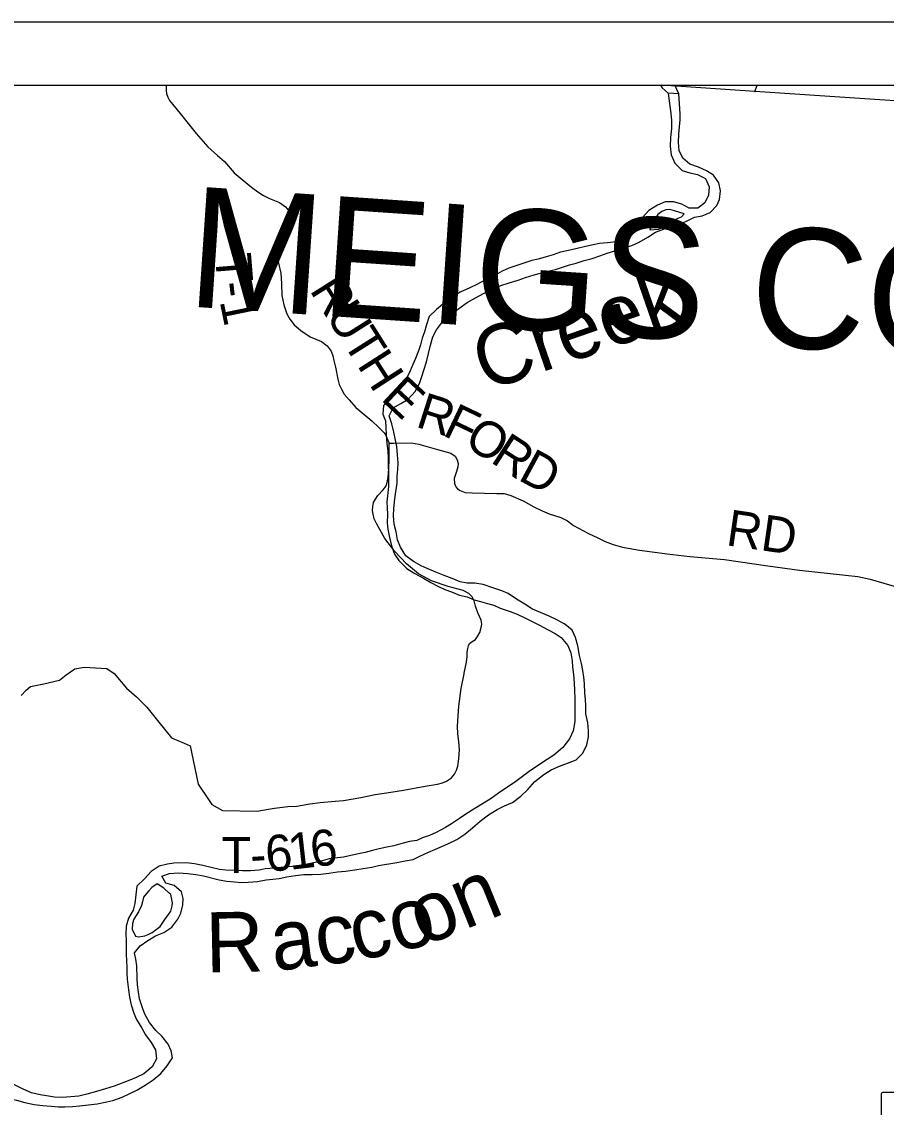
# Model space of a CAD drawing. Extents: x -15 to 405, y -40 to 87.
# Drawn here: x -11.81 to -10.448, y 27.988 to 29.698 of the extents above; entities that cross this region are included whole.
import ezdxf

# ---------------------------------------------------------------- set-up
doc = ezdxf.new("R2010")
doc.units = 0
for name, color, linetype in [('GM_P_State_Location', 7, 'Continuous'), ('GM_P_US_Location', 7, 'Continuous'), ('GM_X_County_Road_Text', 7, 'Continuous'), ('GM_X_Minor_River', 7, 'Continuous'), ('GM_X_Township', 7, 'Continuous'), ('GM_X_Township_Road', 7, 'Continuous'), ('GM_X_Township_Road_Text', 7, 'Continuous'), ('GM_X_Township_Subdivision', 7, 'Continuous')]:
    doc.layers.add(name, color=color, linetype=linetype)

msp = doc.modelspace()

# ---------------------------------------------------------------- linework, layer by layer
at = {"layer": 'GM_P_State_Location'}
msp.add_line((-10.6552, 29.5879), (-10.6519, 29.5981), dxfattribs=at)
for points in [[(-11.5825, 29.5981), (-11.5827, 29.5959), (-11.5829, 29.5898), (-11.5822, 29.585), (-11.5804, 29.5795), (-11.5773, 29.5742), (-11.5608, 29.5537), (-11.5354, 29.522), (-11.5169, 29.5009), (-11.5018, 29.4872), (-11.4911, 29.4778), (-11.4755, 29.4603), (-11.4632, 29.4494), (-11.4485, 29.4374), (-11.4383, 29.4301), (-11.4296, 29.4245), (-11.4199, 29.4195), (-11.404, 29.4132), (-11.3947, 29.4065), (-11.3897, 29.4003), (-11.3867, 29.3929), (-11.3872, 29.3858), (-11.3887, 29.3786), (-11.3902, 29.3734), (-11.3936, 29.3662), (-11.3978, 29.3581), (-11.4042, 29.3457), (-11.4063, 29.339), (-11.4075, 29.3323), (-11.4074, 29.3244), (-11.4056, 29.3176), (-11.4022, 29.3021), (-11.4012, 29.2857), (-11.4007, 29.2671), (-11.3973, 29.2521), (-11.3925, 29.2382), (-11.3879, 29.2297), (-11.3811, 29.2209), (-11.3708, 29.2117), (-11.356, 29.202), (-11.3383, 29.1942), (-11.3291, 29.1875), (-11.323, 29.179), (-11.3201, 29.1718), (-11.3184, 29.1645), (-11.3161, 29.1539), (-11.3122, 29.135), (-11.3101, 29.1269), (-11.3064, 29.1192), (-11.3021, 29.1117), (-11.2947, 29.1024), (-11.2838, 29.0905), (-11.2589, 29.0692), (-11.2477, 29.0588), (-11.2396, 29.0505), (-11.2368, 29.0469), (-11.2354, 29.0429), (-11.2317, 29.0344), (-11.2244, 29.0342), (-11.1962, 29.0347), (-11.1847, 29.0329), (-11.1551, 29.0245), (-11.1343, 29.0186), (-11.1275, 29.0138), (-11.1241, 29.0081), (-11.1228, 29.0021), (-11.1231, 28.997), (-11.1255, 28.9894), (-11.1289, 28.9784), (-11.1283, 28.9706), (-11.1266, 28.9657), (-11.1238, 28.9623), (-11.1198, 28.9595), (-11.1119, 28.9568), (-11.1006, 28.9558), (-11.0618, 28.9551), (-11.0502, 28.9548), (-11.0397, 28.9517), (-11.0203, 28.9432), (-11.0033, 28.9342), (-10.9902, 28.9275), (-10.9793, 28.9228), (-10.9608, 28.917), (-10.9506, 28.9121), (-10.9413, 28.9047), (-10.9176, 28.892), (-10.9026, 28.8849), (-10.8911, 28.8793), (-10.8785, 28.8744), (-10.8639, 28.8704), (-10.8373, 28.8658), (-10.7934, 28.86), (-10.758, 28.856), (-10.7029, 28.8512), (-10.6349, 28.8408), (-10.5852, 28.8343), (-10.5127, 28.8264), (-10.4933, 28.824), (-10.4737, 28.8203), (-10.4521, 28.8139), (-10.4196, 28.8042)], [(-11.5153, 28.4715), (-11.5111, 28.4652), (-11.4938, 28.4557), (-11.4397, 28.4547), (-11.4123, 28.4592), (-11.3913, 28.4619), (-11.3768, 28.4626), (-11.3562, 28.4661), (-11.3401, 28.4684), (-11.3166, 28.4702), (-11.3034, 28.4714), (-11.276, 28.476), (-11.2536, 28.481), (-11.2287, 28.4845), (-11.2087, 28.4877), (-11.1748, 28.494), (-11.1554, 28.4969), (-11.1473, 28.499), (-11.1409, 28.502), (-11.1331, 28.5069), (-11.1284, 28.5127), (-11.1252, 28.5193), (-11.1232, 28.5253), (-11.1216, 28.5373), (-11.1209, 28.5514), (-11.1216, 28.5645), (-11.1232, 28.5763), (-11.1239, 28.5885), (-11.1229, 28.6046), (-11.1215, 28.6199), (-11.1181, 28.6478), (-11.1135, 28.6711), (-11.1134, 28.6719), (-11.1098, 28.6895), (-11.1088, 28.6983), (-11.1084, 28.7049), (-11.1075, 28.7109), (-11.1066, 28.7151), (-11.1047, 28.7185), (-11.1006, 28.7217), (-11.0957, 28.725), (-11.0923, 28.7296), (-11.0886, 28.7361), (-11.0863, 28.7437), (-11.0856, 28.749), (-11.0867, 28.7556), (-11.0918, 28.767), (-11.0955, 28.7776), (-11.0973, 28.7858), (-11.1006, 28.7921), (-11.1061, 28.7976), (-11.1151, 28.8024), (-11.1384, 28.8085), (-11.1649, 28.8174), (-11.185, 28.8285), (-11.2043, 28.8444), (-11.2227, 28.8635), (-11.2384, 28.8843), (-11.2514, 28.9076), (-11.2552, 28.9152), (-11.2567, 28.9223), (-11.2578, 28.9283), (-11.2573, 28.9339), (-11.2562, 28.9406), (-11.2532, 28.9459), (-11.2493, 28.9517), (-11.2407, 28.9608), (-11.2363, 28.9669), (-11.2347, 28.9721), (-11.2333, 28.9802), (-11.2322, 28.9939), (-11.2315, 29.0086), (-11.2317, 29.022), (-11.2317, 29.0344)], [(-11.8113, 28.6369), (-11.8035, 28.645), (-11.7967, 28.6508), (-11.7755, 28.655), (-11.7508, 28.6611), (-11.7401, 28.6693), (-11.7267, 28.6788), (-11.7116, 28.6813), (-11.694, 28.6805), (-11.6761, 28.6793), (-11.6649, 28.6712), (-11.6454, 28.6486), (-11.6295, 28.6347), (-11.613, 28.6182), (-11.5943, 28.595), (-11.5745, 28.5702), (-11.5546, 28.5618), (-11.5452, 28.5576), (-11.5323, 28.497), (-11.5153, 28.4715)]]:
    msp.add_lwpolyline(points, dxfattribs=at)
at = {"layer": 'GM_X_County_Road_Text'}
msp.add_lwpolyline([(-7.293, 29.3749), (-7.5587, 29.3922), (-8.2163, 29.4345), (-8.9822, 29.4843), (-9.3083, 29.5055), (-9.3253, 29.5066), (-9.7655, 29.5289), (-10.6554, 29.5884), (-10.8023, 29.5981)], dxfattribs=at)
at = {"layer": 'GM_X_Township'}
for p, q in [((-14.193, 29.6981), (-7.193, 29.6981)), ((-14.093, 29.5981), (-7.293, 29.5981))]:
    msp.add_line(p, q, dxfattribs=at)
at = {"layer": 'GM_X_Township_Road'}
for q in [(-10.7921, 29.5855), (-10.7813, 29.5981)]:
    msp.add_line((-10.7753, 29.5844), q, dxfattribs=at)
for points in [[(-10.7921, 29.5855), (-10.7876, 29.5535), (-10.7864, 29.5425), (-10.7864, 29.53), (-10.7883, 29.5159), (-10.7886, 29.5019), (-10.7874, 29.4883), (-10.7813, 29.4754), (-10.7696, 29.4637), (-10.7575, 29.4599), (-10.7457, 29.4577), (-10.7332, 29.4509), (-10.7271, 29.438), (-10.7282, 29.4247), (-10.7339, 29.4129), (-10.7452, 29.4042), (-10.7589, 29.4045), (-10.7702, 29.4106), (-10.7835, 29.4143), (-10.7967, 29.4143), (-10.8085, 29.4093), (-10.8221, 29.4006), (-10.833, 29.3892), (-10.8417, 29.3774), (-10.8492, 29.3645), (-10.8613, 29.3542), (-10.8738, 29.3515), (-10.8874, 29.3496), (-10.9003, 29.3488), (-10.9102, 29.3469), (-10.9219, 29.3438), (-10.9351, 29.3407), (-10.9491, 29.3377), (-10.9616, 29.335), (-10.9733, 29.3308), (-10.9839, 29.3277), (-10.9968, 29.3239), (-11.0066, 29.3219), (-11.0429, 29.3097), (-11.0535, 29.3051), (-11.0645, 29.2987), (-11.0785, 29.2922), (-11.0932, 29.2842), (-11.1042, 29.2788), (-11.1197, 29.272), (-11.1329, 29.2643), (-11.1439, 29.256), (-11.1567, 29.2449), (-11.1684, 29.2339), (-11.1733, 29.2191), (-11.176, 29.2096), (-11.1794, 29.1998), (-11.182, 29.1891), (-11.1854, 29.1796), (-11.1899, 29.1675), (-11.194, 29.158), (-11.1997, 29.1443), (-11.2065, 29.1326), (-11.2163, 29.1189), (-11.2291, 29.1067), (-11.2404, 29.0934), (-11.2416, 29.0798), (-11.2374, 29.0695), (-11.2366, 29.0597), (-11.2362, 29.0468), (-11.235, 29.0339), (-11.2335, 29.0214), (-11.2331, 29.0115), (-11.233, 28.999), (-11.2326, 28.9865), (-11.2326, 28.9661), (-11.2341, 28.9513), (-11.2352, 28.9418), (-11.2348, 28.9323), (-11.234, 28.9225), (-11.2344, 28.9084), (-11.2336, 28.8989), (-11.2309, 28.8857), (-11.2278, 28.8724), (-11.2233, 28.8596), (-11.2161, 28.8497), (-11.2035, 28.8369), (-11.191, 28.8289), (-11.1774, 28.8214), (-11.1656, 28.8146), (-11.155, 28.8089), (-11.144, 28.804), (-11.1334, 28.7999), (-11.1205, 28.795), (-11.1088, 28.792), (-11.0974, 28.7875), (-11.0876, 28.7849), (-11.0766, 28.7819), (-11.0664, 28.7789), (-11.0565, 28.7743), (-11.0406, 28.7691), (-11.0296, 28.7649), (-11.0175, 28.7593), (-11.0073, 28.754), (-10.9948, 28.7476)], [(-10.8039, 29.5981), (-10.8013, 29.594), (-10.7921, 29.5855)], [(-10.7728, 29.5529), (-10.7753, 29.5844)], [(-10.9429, 28.7398), (-10.9546, 28.7492), (-10.9672, 28.756), (-10.9793, 28.7617), (-11.0058, 28.773), (-11.0179, 28.7809), (-11.0308, 28.7884), (-11.0441, 28.7975), (-11.0539, 28.8016), (-11.068, 28.8065), (-11.0835, 28.8114), (-11.0967, 28.8137), (-11.1085, 28.814), (-11.1198, 28.8159), (-11.132, 28.8211), (-11.1448, 28.8256), (-11.1577, 28.8309), (-11.1714, 28.8369), (-11.1808, 28.8411), (-11.1933, 28.8479), (-11.2051, 28.8569), (-11.2138, 28.8702), (-11.2184, 28.8819), (-11.2203, 28.8948), (-11.2234, 28.9069), (-11.2245, 28.9198), (-11.2242, 28.9316), (-11.2223, 28.9467), (-11.2208, 28.9577), (-11.219, 28.971), (-11.2186, 28.9824), (-11.2179, 28.993), (-11.2175, 29.0033), (-11.2183, 29.0161), (-11.2195, 29.029), (-11.2241, 29.0518), (-11.2275, 29.0646), (-11.2313, 29.0771), (-11.2253, 29.0897), (-11.2132, 29.0965), (-11.2015, 29.1034), (-11.1905, 29.1156), (-11.1837, 29.1285), (-11.1804, 29.1379), (-11.1762, 29.1509), (-11.1725, 29.1626), (-11.1661, 29.1884), (-11.1627, 29.2017), (-11.157, 29.2127), (-11.1476, 29.2252), (-11.1355, 29.2363), (-11.1219, 29.2462), (-11.1087, 29.2557), (-11.0955, 29.2633), (-11.0818, 29.2705), (-11.0679, 29.277), (-11.0554, 29.2828), (-11.0425, 29.2866), (-11.0281, 29.2908), (-11.0168, 29.295), (-11.0032, 29.2992), (-10.993, 29.3019), (-10.9816, 29.3053), (-10.9695, 29.308), (-10.9597, 29.3107), (-10.9476, 29.3153), (-10.9366, 29.318), (-10.9241, 29.3218), (-10.9116, 29.3252), (-10.8995, 29.3294), (-10.8882, 29.3337), (-10.8761, 29.3371), (-10.8636, 29.3413), (-10.8492, 29.3455), (-10.8375, 29.3509), (-10.8239, 29.3585), (-10.8118, 29.3665), (-10.7993, 29.3714), (-10.7872, 29.3749), (-10.7758, 29.3787), (-10.763, 29.3841), (-10.7505, 29.3902), (-10.7384, 29.3925), (-10.7255, 29.3974), (-10.715, 29.4088), (-10.7112, 29.4183), (-10.7093, 29.4316), (-10.712, 29.4441), (-10.7204, 29.4562), (-10.7317, 29.4634), (-10.7442, 29.469), (-10.7575, 29.4739), (-10.7689, 29.483), (-10.7746, 29.4951), (-10.7754, 29.5076), (-10.775, 29.5209), (-10.7739, 29.5327), (-10.7728, 29.5433), (-10.7728, 29.5529)], [(-10.7668, 29.3954), (-10.7736, 29.3977), (-10.7819, 29.4003), (-10.7895, 29.4022), (-10.7956, 29.4018), (-10.802, 29.3991), (-10.8084, 29.3942), (-10.8133, 29.3866), (-10.8163, 29.3805), (-10.8209, 29.3702)], [(-10.8209, 29.3702), (-10.8065, 29.3714), (-10.7997, 29.3748), (-10.7929, 29.3787), (-10.7864, 29.3836), (-10.7804, 29.3863), (-10.7759, 29.3886), (-10.7709, 29.3909), (-10.7668, 29.3954)], [(-10.9948, 28.7476), (-10.9819, 28.7408), (-10.9701, 28.7344), (-10.9607, 28.7284), (-10.95, 28.7155), (-10.9455, 28.7041), (-10.9432, 28.6913), (-10.9424, 28.6818), (-10.9412, 28.6697), (-10.9401, 28.656), (-10.9397, 28.645), (-10.9392, 28.6314), (-10.9392, 28.5957), (-10.9418, 28.5813), (-10.9474, 28.5684), (-10.958, 28.5551), (-10.972, 28.5426), (-10.9826, 28.5361), (-11.0087, 28.5186), (-11.0215, 28.5094), (-11.034, 28.4996), (-11.0476, 28.4908), (-11.0593, 28.4832), (-11.0706, 28.4744), (-11.082, 28.4679), (-11.0967, 28.4588), (-11.1107, 28.4501), (-11.1205, 28.4432), (-11.133, 28.4348), (-11.1428, 28.4287), (-11.1576, 28.4211), (-11.1678, 28.4165), (-11.178, 28.4131), (-11.1878, 28.4085), (-11.1992, 28.4066), (-11.2094, 28.4043), (-11.2242, 28.4001), (-11.2351, 28.3978), (-11.2472, 28.3951), (-11.2578, 28.3928), (-11.2692, 28.3897), (-11.2798, 28.3874), (-11.2919, 28.3847), (-11.3032, 28.3824), (-11.3131, 28.3812), (-11.326, 28.3793), (-11.3369, 28.3766), (-11.3528, 28.3728), (-11.3634, 28.3705), (-11.3732, 28.3689), (-11.3838, 28.3674), (-11.3975, 28.3662), (-11.4115, 28.3647), (-11.4266, 28.3639), (-11.4364, 28.3616), (-11.4501, 28.3608), (-11.4626, 28.3607), (-11.4758, 28.3611), (-11.4887, 28.3618), (-11.4989, 28.3629), (-11.5118, 28.3659), (-11.525, 28.3689), (-11.5379, 28.3719), (-11.5508, 28.373), (-11.5705, 28.3729), (-11.5807, 28.371), (-11.5936, 28.3679), (-11.6064, 28.3596), (-11.617, 28.3481), (-11.6291, 28.3367), (-11.6306, 28.3227), (-11.632, 28.3091), (-11.635, 28.2988), (-11.6422, 28.2859), (-11.6456, 28.2734), (-11.6463, 28.2609), (-11.6459, 28.2514), (-11.6459, 28.2298), (-11.6455, 28.2184), (-11.6447, 28.2089), (-11.6447, 28.1995), (-11.6443, 28.19), (-11.6423, 28.1733), (-11.6408, 28.1619), (-11.6381, 28.1498), (-11.6339, 28.1362), (-11.6294, 28.1263), (-11.621, 28.1127), (-11.6153, 28.1025), (-11.6062, 28.0904), (-11.5994, 28.0786), (-11.5978, 28.0646), (-11.6046, 28.0521), (-11.6178, 28.0411), (-11.6303, 28.0353), (-11.6401, 28.0308), (-11.6647, 28.0212), (-11.6783, 28.0174), (-11.6927, 28.0128), (-11.7078, 28.0086), (-11.7203, 28.0059)], [(-11.6522, 28.0042), (-11.6412, 28.0092), (-11.6291, 28.0153), (-11.6159, 28.0229), (-11.6034, 28.0316), (-11.5913, 28.0415), (-11.5811, 28.0533), (-11.5728, 28.0662), (-11.5748, 28.0772), (-11.5797, 28.0878), (-11.5896, 28.1003), (-11.599, 28.1094), (-11.6093, 28.1215), (-11.6165, 28.1347), (-11.6203, 28.1449), (-11.6249, 28.1589), (-11.6264, 28.1696), (-11.628, 28.1813), (-11.6287, 28.1908), (-11.6288, 28.2109), (-11.6307, 28.2215), (-11.6326, 28.2313), (-11.6236, 28.2427), (-11.6115, 28.2511), (-11.5994, 28.258), (-11.5865, 28.2633), (-11.574, 28.2717), (-11.5642, 28.2846), (-11.5597, 28.2941), (-11.5567, 28.307), (-11.556, 28.3172), (-11.5586, 28.3278), (-11.5704, 28.3373), (-11.5833, 28.3414), (-11.5897, 28.352), (-11.5776, 28.3562), (-11.5632, 28.3574), (-11.5485, 28.3563), (-11.536, 28.3548), (-11.5242, 28.3526), (-11.4993, 28.3466), (-11.4871, 28.3443), (-11.475, 28.3432), (-11.464, 28.3421), (-11.4534, 28.3429), (-11.4387, 28.3437), (-11.4254, 28.3464), (-11.4145, 28.3476), (-11.4046, 28.3488), (-11.3925, 28.3514), (-11.3789, 28.3534), (-11.366, 28.3546), (-11.3528, 28.355), (-11.3391, 28.3554), (-11.3263, 28.3569), (-11.313, 28.3589), (-11.3005, 28.36), (-11.2854, 28.3624), (-11.2722, 28.3643), (-11.2589, 28.3666), (-11.2483, 28.3689), (-11.2196, 28.3735), (-11.2063, 28.3762), (-11.1935, 28.3785), (-11.1833, 28.3839), (-11.1693, 28.39), (-11.1594, 28.3942), (-11.139, 28.4033), (-11.125, 28.4102), (-11.1122, 28.4186), (-11.1001, 28.4285), (-11.088, 28.4391), (-11.0751, 28.4486), (-11.0615, 28.457), (-11.0498, 28.4631), (-11.0369, 28.4685), (-11.0241, 28.4784), (-11.0128, 28.489), (-11.0022, 28.5012), (-10.9878, 28.5126), (-10.9761, 28.5198), (-10.9629, 28.5255), (-10.9504, 28.5301), (-10.9371, 28.5355), (-10.9266, 28.5461), (-10.9198, 28.559), (-10.9175, 28.5719), (-10.9172, 28.5814), (-10.9183, 28.5939), (-10.9214, 28.6079), (-10.9218, 28.6208), (-10.9222, 28.6303), (-10.9234, 28.6405), (-10.9238, 28.6557), (-10.9249, 28.6659), (-10.9265, 28.6761), (-10.9284, 28.6871), (-10.9314, 28.7), (-10.9341, 28.7148), (-10.9379, 28.7284), (-10.9429, 28.7398)], [(-11.5969, 28.3399), (-11.6052, 28.3345), (-11.6101, 28.3292), (-11.6139, 28.325), (-11.6184, 28.319), (-11.6203, 28.3117), (-11.6218, 28.3061), (-11.6263, 28.2962), (-11.6339, 28.2844), (-11.6358, 28.2776), (-11.6365, 28.2685), (-11.6312, 28.2579)], [(-11.6312, 28.2579), (-11.6262, 28.2568), (-11.6198, 28.2575), (-11.6164, 28.2583), (-11.6111, 28.2602), (-11.6047, 28.2636), (-11.5983, 28.2682), (-11.5922, 28.2732), (-11.585, 28.2842), (-11.579, 28.2918), (-11.5756, 28.2971), (-11.5734, 28.3054), (-11.573, 28.31), (-11.5757, 28.3232), (-11.5779, 28.3255), (-11.5863, 28.3331), (-11.5969, 28.3399)], [(-11.7203, 28.0059), (-11.7328, 28.0047), (-11.7464, 28.0035), (-11.7586, 28.0039), (-11.7714, 28.0061), (-11.7813, 28.0076), (-11.7949, 28.011), (-11.8082, 28.0166), (-11.8226, 28.0242), (-11.8362, 28.0306), (-11.8495, 28.0359), (-11.8627, 28.0407), (-11.8737, 28.0447)], [(-11.9009, 28.0277), (-11.8877, 28.0187), (-11.8759, 28.0142), (-11.8642, 28.0123), (-11.8513, 28.0097), (-11.8392, 28.0056), (-11.8297, 28.0018), (-11.8184, 27.9992), (-11.8055, 27.9958), (-11.7907, 27.9928), (-11.7771, 27.9909), (-11.7642, 27.9898), (-11.7525, 27.9891), (-11.7426, 27.9891), (-11.7305, 27.9896), (-11.7192, 27.9907), (-11.7052, 27.9923), (-11.6915, 27.9938), (-11.6764, 27.9969), (-11.6666, 27.9988), (-11.6522, 28.0042)]]:
    msp.add_lwpolyline(points, dxfattribs=at)
at = {"layer": 'GM_X_Township_Subdivision'}
for p, q in [((-10.3763, 28.0117), (-10.4535, 28.0117)), ((-10.4561, 28.0082), (-10.4561, 27.8081))]:
    msp.add_line(p, q, dxfattribs=at)
msp.add_arc((-10.4531, 28.0086), 0.00305, 98.1301, 188.1301, dxfattribs=at)

# ---------------------------------------------------------------- texts
at = {"layer": 'GM_P_US_Location'}
msp.add_text('MEIGS COUNTY', height=0.189394, rotation=356.1113, dxfattribs=at).set_placement((-11.5522, 29.2499))
at = {"layer": 'GM_X_Minor_River'}
for s, height, rotation, p in [('T', 0.0568, 274.6248, (-11.506, 29.3312)), ('R', 0.0568, 302.319, (-11.3577, 29.2752)), ('-', 0.0568, 276.9198, (-11.5023, 29.2864)), ('1', 0.0568, 281.6376, (-11.4987, 29.2582)), ('U', 0.0568, 302.3208, (-11.3327, 29.2358)), ('T', 0.0568, 302.3207, (-11.306, 29.1936)), ('H', 0.0568, 302.7166, (-11.283, 29.1573)), ('E', 0.0568, 317.0494, (-11.2461, 29.1033)), ('R', 0.0568, 342.3324, (-11.1915, 29.0607)), ('F', 0.0568, 334.5123, (-11.149, 29.0473)), ('O', 0.0568, 328.0894, (-11.1158, 29.0316)), ('R', 0.0568, 327.0439, (-11.0736, 29.0053)), ('D', 0.0568, 331.5761, (-11.0302, 28.9774)), ('RD', 0.05682, 351.7984, (-10.7022, 28.8737)), ('6', 0.0568, 5.1433, (-11.424, 28.3589)), ('1', 0.0568, 6.5284, (-11.3877, 28.3622)), ('6', 0.0568, 6.8816, (-11.3525, 28.3662)), ('T', 0.0568, 359.9957, (-11.4954, 28.3572)), ('-', 0.0568, 3.7069, (-11.4488, 28.3573))]:
    msp.add_text(s, height=height, rotation=rotation, dxfattribs=at).set_placement(p)
at = {"layer": 'GM_X_Township_Road_Text'}
for s, height, rotation, p in [('Creek', 0.0947, 19.0988, (-11.0794, 29.1152)), ('on', 0.09469, 22.0989, (-11.1778, 28.2412)), ('co', 0.0947, 13.1008, (-11.2832, 28.2177)), ('R', 0.0947, 1.1029, (-11.52, 28.2005)), ('ac', 0.0947, 7.102, (-11.4131, 28.2025))]:
    msp.add_text(s, height=height, rotation=rotation, dxfattribs=at).set_placement(p)

doc.saveas('drawing.dxf')
